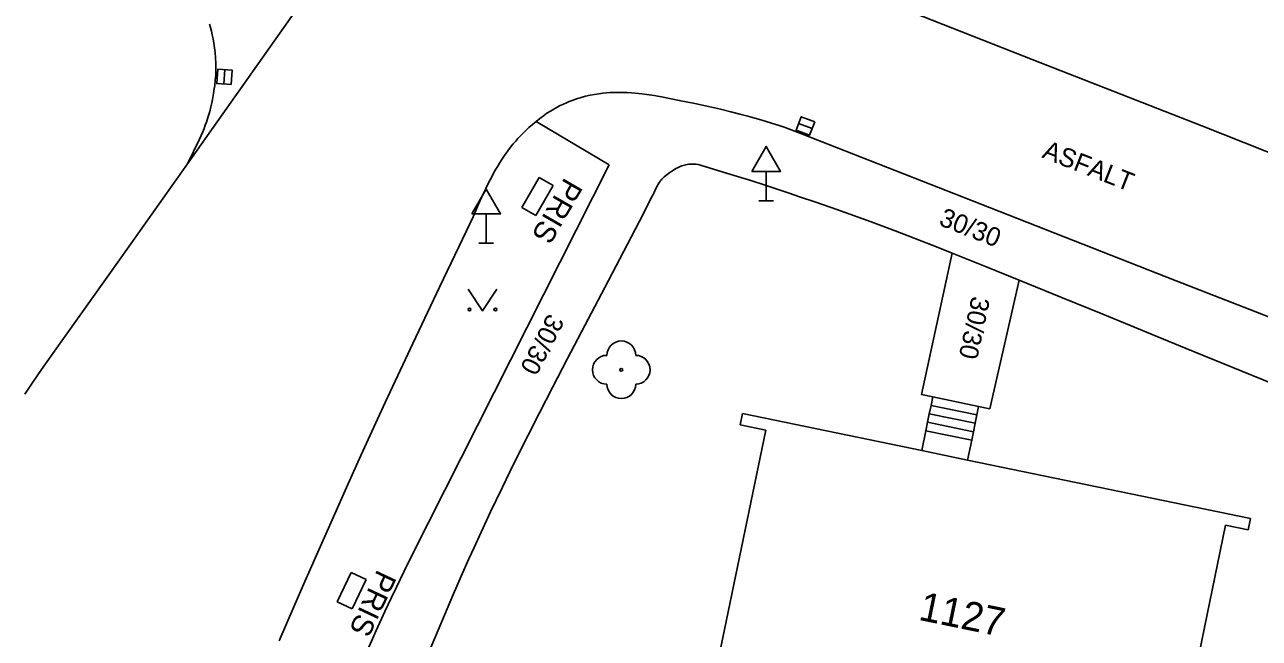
# Model space of a CAD drawing. Extents: x -538441 to -536770, y -1181008 to -1179809.
# Drawn here: x -538327.77 to -538284.91, y -1180774.19 to -1180752.9 of the extents above; entities that cross this region are included whole.
import ezdxf

# ---------------------------------------------------------------- set-up
doc = ezdxf.new("R2010")
doc.units = 0
for name, color, linetype in [('Vrstva 10', 7, 'Continuous'), ('Vrstva 11', 7, 'Continuous'), ('Vrstva 22', 7, 'Continuous'), ('Vrstva 24', 7, 'Continuous'), ('Vrstva 27', 7, 'Continuous'), ('Vrstva 34', 7, 'Continuous'), ('Vrstva 36', 7, 'Continuous'), ('Vrstva 40', 7, 'Continuous'), ('Vrstva 41', 7, 'Continuous'), ('Vrstva 47', 7, 'Continuous'), ('Vrstva 5', 7, 'Continuous')]:
    doc.layers.add(name, color=color, linetype=linetype)

msp = doc.modelspace()

# ---------------------------------------------------------------- linework, layer by layer
at = {"layer": 'Vrstva 10'}
for p, q in [((-538317.14, -1180750.674), (-538322.12, -1180757.72)), ((-538292.801, -1180754.098), (-538298.69, -1180751.78)), ((-538286.91, -1180756.41), (-538292.801, -1180754.098)), ((-538301.07, -1180756.576), (-538300.77, -1180756.69)), ((-538300.77, -1180756.69), (-538294.284, -1180759.236)), ((-538279.428, -1180759.376), (-538286.91, -1180756.41)), ((-538294.284, -1180759.236), (-538287.8, -1180761.78)), ((-538287.8, -1180761.78), (-538282.615, -1180763.81))]:
    msp.add_line(p, q, dxfattribs=at)
for points in [[(-538309.178, -1180755.701), (-538309.07, -1180755.649), (-538308.966, -1180755.602), (-538308.864, -1180755.56), (-538308.764, -1180755.522), (-538308.668, -1180755.487), (-538308.575, -1180755.456), (-538308.484, -1180755.429), (-538308.308, -1180755.381), (-538308.142, -1180755.343), (-538307.986, -1180755.314), (-538307.84, -1180755.291), (-538307.703, -1180755.274), (-538307.574, -1180755.262), (-538307.453, -1180755.253), (-538307.34, -1180755.247), (-538307.234, -1180755.244), (-538307.035, -1180755.244), (-538306.861, -1180755.249), (-538306.709, -1180755.257), (-538306.577, -1180755.267), (-538306.346, -1180755.291), (-538306.173, -1180755.313), (-538305.915, -1180755.353), (-538305.66, -1180755.4), (-538305.046, -1180755.522), (-538304.506, -1180755.634), (-538304.032, -1180755.737), (-538303.618, -1180755.832), (-538303.256, -1180755.919), (-538302.94, -1180755.999), (-538302.664, -1180756.072), (-538302.423, -1180756.139), (-538302.214, -1180756.2), (-538301.848, -1180756.311), (-538301.576, -1180756.399), (-538301.373, -1180756.468), (-538301.07, -1180756.576)], [(-538310.27, -1180756.467), (-538310.148, -1180756.358), (-538310.02, -1180756.25), (-538309.89, -1180756.147), (-538309.764, -1180756.054), (-538309.641, -1180755.969), (-538309.52, -1180755.891), (-538309.403, -1180755.822), (-538309.289, -1180755.758), (-538309.178, -1180755.701)], [(-538314.905, -1180765.263), (-538314.292, -1180763.96), (-538313.365, -1180762.007), (-538312.432, -1180760.054), (-538312.313, -1180759.8), (-538312.206, -1180759.563), (-538312.012, -1180759.124), (-538311.84, -1180758.744), (-538311.763, -1180758.579), (-538311.689, -1180758.426), (-538311.617, -1180758.283), (-538311.547, -1180758.15), (-538311.48, -1180758.025), (-538311.414, -1180757.909), (-538311.351, -1180757.801), (-538311.289, -1180757.7), (-538311.229, -1180757.606), (-538311.112, -1180757.43), (-538311.002, -1180757.278), (-538310.901, -1180757.146), (-538310.808, -1180757.031), (-538310.723, -1180756.932), (-538310.646, -1180756.845), (-538310.576, -1180756.769), (-538310.448, -1180756.638), (-538310.348, -1180756.54), (-538310.27, -1180756.467)], [(-538322.12, -1180757.72), (-538324.484, -1180761.055), (-538326.85, -1180764.39), (-538327.181, -1180764.861), (-538327.487, -1180765.303), (-538327.77, -1180765.72)], [(-538318.934, -1180774.277), (-538318.425, -1180773.096), (-538318.04, -1180772.212), (-538317.457, -1180770.886), (-538316.87, -1180769.56), (-538316.603, -1180768.96), (-538316.096, -1180767.839), (-538315.649, -1180766.862), (-538315.253, -1180766.008), (-538314.905, -1180765.263)]]:
    msp.add_lwpolyline(points, dxfattribs=at)
at = {"layer": 'Vrstva 11'}
for p, q in [((-538307.48, -1180757.76), (-538310.02, -1180756.25)), ((-538310.905, -1180764.54), (-538307.48, -1180757.76)), ((-538295.58, -1180760.82), (-538296.64, -1180765.73)), ((-538293.25, -1180761.76), (-538294.265, -1180766.221)), ((-538314.33, -1180771.32), (-538310.905, -1180764.54)), ((-538296.64, -1180765.73), (-538296.248, -1180765.811)), ((-538294.715, -1180766.433), (-538296.308, -1180766.104)), ((-538294.655, -1180766.14), (-538296.248, -1180765.811)), ((-538294.776, -1180766.727), (-538296.369, -1180766.398)), ((-538294.265, -1180766.221), (-538294.655, -1180766.14)), ((-538294.837, -1180767.021), (-538296.43, -1180766.692)), ((-538294.897, -1180767.315), (-538296.49, -1180766.986)), ((-538312.88, -1180772.64), (-538315.112, -1180777.878))]:
    msp.add_line(p, q, dxfattribs=at)
for points in [[(-538322.12, -1180757.72), (-538321.913, -1180757.295), (-538321.706, -1180756.87), (-538321.645, -1180756.74), (-538321.591, -1180756.616), (-538321.543, -1180756.498), (-538321.501, -1180756.387), (-538321.463, -1180756.281), (-538321.398, -1180756.08), (-538321.347, -1180755.903), (-538321.307, -1180755.747), (-538321.275, -1180755.609), (-538321.25, -1180755.489), (-538321.211, -1180755.278), (-538321.187, -1180755.119), (-538321.172, -1180755.001), (-538321.153, -1180754.825), (-538321.14, -1180754.65), (-538321.135, -1180754.541), (-538321.132, -1180754.435), (-538321.132, -1180754.333), (-538321.134, -1180754.234), (-538321.143, -1180754.042), (-538321.16, -1180753.862), (-538321.18, -1180753.693), (-538321.205, -1180753.535), (-538321.232, -1180753.386), (-538321.261, -1180753.247), (-538321.291, -1180753.117), (-538321.322, -1180752.994), (-538321.353, -1180752.88)], [(-538299.128, -1180759.471), (-538299.776, -1180759.242), (-538300.342, -1180759.045), (-538300.839, -1180758.875), (-538301.273, -1180758.729), (-538302.033, -1180758.479), (-538302.603, -1180758.296), (-538303.031, -1180758.161), (-538303.671, -1180757.963), (-538304.31, -1180757.77), (-538304.388, -1180757.75), (-538304.462, -1180757.738), (-538304.532, -1180757.731), (-538304.597, -1180757.73), (-538304.659, -1180757.733), (-538304.716, -1180757.739), (-538304.771, -1180757.747), (-538304.821, -1180757.758), (-538304.869, -1180757.77), (-538304.958, -1180757.798), (-538305.036, -1180757.828), (-538305.104, -1180757.859), (-538305.163, -1180757.89), (-538305.215, -1180757.919), (-538305.305, -1180757.974), (-538305.372, -1180758.021), (-538305.471, -1180758.096), (-538305.57, -1180758.18), (-538305.613, -1180758.22), (-538305.65, -1180758.258), (-538305.681, -1180758.294), (-538305.708, -1180758.328), (-538305.754, -1180758.391), (-538305.789, -1180758.447), (-538305.817, -1180758.496), (-538305.86, -1180758.583), (-538305.921, -1180758.716), (-538305.952, -1180758.783), (-538305.985, -1180758.851), (-538306.427, -1180759.71), (-538306.844, -1180760.513)], [(-538296.625, -1180760.407), (-538297.101, -1180760.223), (-538297.549, -1180760.053), (-538298.39, -1180759.739), (-538299.128, -1180759.471)], [(-538306.844, -1180760.513), (-538307.631, -1180762.015), (-538308.322, -1180763.328), (-538308.925, -1180764.477), (-538309.449, -1180765.484), (-538309.903, -1180766.367), (-538310.297, -1180767.141), (-538310.637, -1180767.82), (-538310.932, -1180768.416), (-538311.187, -1180768.938), (-538311.408, -1180769.397)], [(-538287.452, -1180764.129), (-538290.349, -1180762.938), (-538291.798, -1180762.346), (-538293.25, -1180761.76), (-538294.414, -1180761.291), (-538295.58, -1180760.82), (-538296.119, -1180760.605), (-538296.625, -1180760.407)], [(-538278.33, -1180767.71), (-538279.273, -1180767.365), (-538280.154, -1180767.036), (-538280.979, -1180766.722), (-538281.75, -1180766.424), (-538282.472, -1180766.141), (-538283.149, -1180765.874), (-538284.414, -1180765.367), (-538285.52, -1180764.919), (-538287.452, -1180764.129)], [(-538296.633, -1180767.673), (-538296.49, -1180766.986), (-538296.43, -1180766.692), (-538296.369, -1180766.398), (-538296.308, -1180766.104), (-538296.248, -1180765.811)], [(-538295.04, -1180768.002), (-538294.897, -1180767.315), (-538294.837, -1180767.021), (-538294.776, -1180766.727), (-538294.715, -1180766.433), (-538294.655, -1180766.14)], [(-538311.408, -1180769.397), (-538311.599, -1180769.799), (-538311.93, -1180770.504)], [(-538311.93, -1180770.504), (-538312.173, -1180771.035), (-538312.353, -1180771.435), (-538312.619, -1180772.036), (-538312.88, -1180772.64)], [(-538316.959, -1180777.167), (-538316.652, -1180776.426), (-538316.38, -1180775.78), (-538316.138, -1180775.215), (-538315.924, -1180774.723), (-538315.735, -1180774.293), (-538315.567, -1180773.918), (-538315.268, -1180773.263), (-538315.04, -1180772.775), (-538314.866, -1180772.409), (-538314.601, -1180771.863), (-538314.33, -1180771.32)]]:
    msp.add_lwpolyline(points, dxfattribs=at)
at = {"layer": 'Vrstva 22'}
msp.add_circle((-538307.06, -1180764.87), 0.05, dxfattribs=at)
for centre, start, end in [((-538307.06, -1180764.37), 0, 180), ((-538307.56, -1180764.87), 90, 270), ((-538306.56, -1180764.87), 270, 90), ((-538307.06, -1180765.37), 180, 0)]:
    msp.add_arc(centre, 0.5, start, end, dxfattribs=at)
at = {"layer": 'Vrstva 24'}
for p, q in [((-538310.51, -1180759.24), (-538309.911, -1180758.202)), ((-538309.911, -1180758.202), (-538309.43, -1180758.48)), ((-538309.43, -1180758.48), (-538310.029, -1180759.518)), ((-538310.029, -1180759.518), (-538310.51, -1180759.24)), ((-538316.44, -1180771.9), (-538316.922, -1180772.924)), ((-538315.918, -1180772.146), (-538316.44, -1180771.9)), ((-538316.4, -1180773.17), (-538315.918, -1180772.146)), ((-538316.922, -1180772.924), (-538316.4, -1180773.17))]:
    msp.add_line(p, q, dxfattribs=at)
at = {"layer": 'Vrstva 27'}
for p, q in [((-538320.852, -1180754.954), (-538320.822, -1180754.454)), ((-538300.437, -1180756.5), (-538300.903, -1180756.32))]:
    msp.add_line(p, q, dxfattribs=at)
for points in [[(-538320.603, -1180754.969), (-538320.572, -1180754.47), (-538321.071, -1180754.439), (-538321.102, -1180754.938)], [(-538300.347, -1180756.266), (-538300.814, -1180756.087), (-538300.993, -1180756.554), (-538300.526, -1180756.733)]]:
    msp.add_lwpolyline(points, close=True, dxfattribs=at)
at = {"layer": 'Vrstva 34'}
for p, q in [((-538302.03, -1180757.988), (-538302.03, -1180759.006)), ((-538302.28, -1180759.006), (-538301.78, -1180759.006)), ((-538311.75, -1180759.464), (-538311.75, -1180760.482)), ((-538312, -1180760.482), (-538311.5, -1180760.482))]:
    msp.add_line(p, q, dxfattribs=at)
for points in [[(-538302.53, -1180757.988), (-538301.53, -1180757.988), (-538302.03, -1180757.122)], [(-538312.25, -1180759.464), (-538311.25, -1180759.464), (-538311.75, -1180758.598)]]:
    msp.add_lwpolyline(points, close=True, dxfattribs=at)
at = {"layer": 'Vrstva 36'}
msp.add_lwpolyline([(-538312.379, -1180762.077), (-538311.879, -1180762.827), (-538311.379, -1180762.077)], dxfattribs=at)
for centre in [(-538312.329, -1180762.777), (-538311.43, -1180762.777)]:
    msp.add_circle(centre, 0.05, dxfattribs=at)
at = {"layer": 'Vrstva 5'}
for p, q in [((-538302.849, -1180766.39), (-538302.93, -1180766.781)), ((-538296.633, -1180767.673), (-538302.849, -1180766.39)), ((-538302.047, -1180766.963), (-538305.382, -1180783.117)), ((-538302.047, -1180766.963), (-538302.93, -1180766.781)), ((-538295.04, -1180768.002), (-538296.633, -1180767.673)), ((-538285.219, -1180770.03), (-538295.04, -1180768.002)), ((-538288.737, -1180783.117), (-538286.083, -1180770.259)), ((-538285.3, -1180770.421), (-538286.083, -1180770.259)), ((-538285.219, -1180770.03), (-538285.3, -1180770.421))]:
    msp.add_line(p, q, dxfattribs=at)

# ---------------------------------------------------------------- texts
at = {"layer": 'Vrstva 40'}
for s, rotation, p in [('ASFALT', 338.5762, (-538292.487, -1180757.495)), ('30/30', 338.5571, (-538296.071, -1180759.837)), ('30/30', 257.8176, (-538294.89, -1180762.289)), ('30/30', 242.6998, (-538309.592, -1180762.883))]:
    msp.add_text(s, height=0.65, rotation=rotation, dxfattribs=at).set_placement(p)
at = {"layer": 'Vrstva 41'}
for rotation, p in [(240.012, (-538309.019, -1180758.167)), (244.7935, (-538315.52, -1180771.769))]:
    msp.add_text('PRIS', height=0.75, rotation=rotation, dxfattribs=at).set_placement(p)
at = {"layer": 'Vrstva 47'}
msp.add_text('1127', height=1, rotation=348.3343, dxfattribs=at).set_placement((-538296.776, -1180773.541))

doc.saveas('drawing.dxf')
